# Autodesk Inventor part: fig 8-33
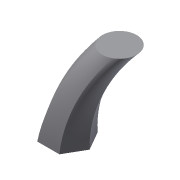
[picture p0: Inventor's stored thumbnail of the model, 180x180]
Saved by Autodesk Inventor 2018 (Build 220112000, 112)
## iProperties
Shininess: 77.0
Angle Display Precision: 2
Document Length Units: 11269
Document Angle Units: 11279
Document Time Units: 11290
Document Mass Units: 11283
Document Length Units Precision: 3
Document Angle Units Precision: 2
Created: 2001-12
Part Number: fig 8-33
Document SubType Name: Modeling
Designer: CADSoft
Density: 1 g/cm^3
Material: Generic
Appearance: Default
Density: 0.0
Volumn: 0.0
Area: 0.0
PropertySet Name: Model Information
Control State: 0
Master: False
Checked Out: False
Author: CADSoft
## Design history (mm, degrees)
workplane "Work Plane3"
workplane "Work Plane4"
sketch "Sketch12"
  geometry: L1 (0, 10.598)-(9.178, -5.299); L2 (9.178, -5.299)-(-9.178, -5.299); L3 (-9.178, -5.299)-(0, 10.598); 1 further point
  constraints: 6 end point, 5 other
workplane "Work Plane5"
workplane "Work Plane6"
workplane "Work Plane7"
sketch "Sketch16"
  geometry: A1 r 72.799 centre (23.007, 110.594) between (0, 41.527) and (70, 54.995); 1 further point
  constraints: 2 point on circle, 1 centre point
loft "Loft5" sketch "Sketch16" dims "d57" = 0, "d58" = 90 deg, "d59" = 0, "d60" = 90 deg, "d61" = 0, "d62" = 90 deg
body "Solid2"
sketch "Sketch1"
  geometry: L1 (19.387, 0)-(9.693, -16.79); L2 (9.693, -16.79)-(-9.693, -16.79); L3 (-9.693, -16.79)-(-19.387, 0); L4 (-19.387, 0)-(-9.693, 16.79); L5 (-9.693, 16.79)-(9.693, 16.79); L6 (9.693, 16.79)-(19.387, 0); 1 further point
  constraints: 12 end point, 11 other
sketch "Sketch2"
  geometry: C1 r 15 at (23.06, 22.535)
  constraints: 1 centre point
